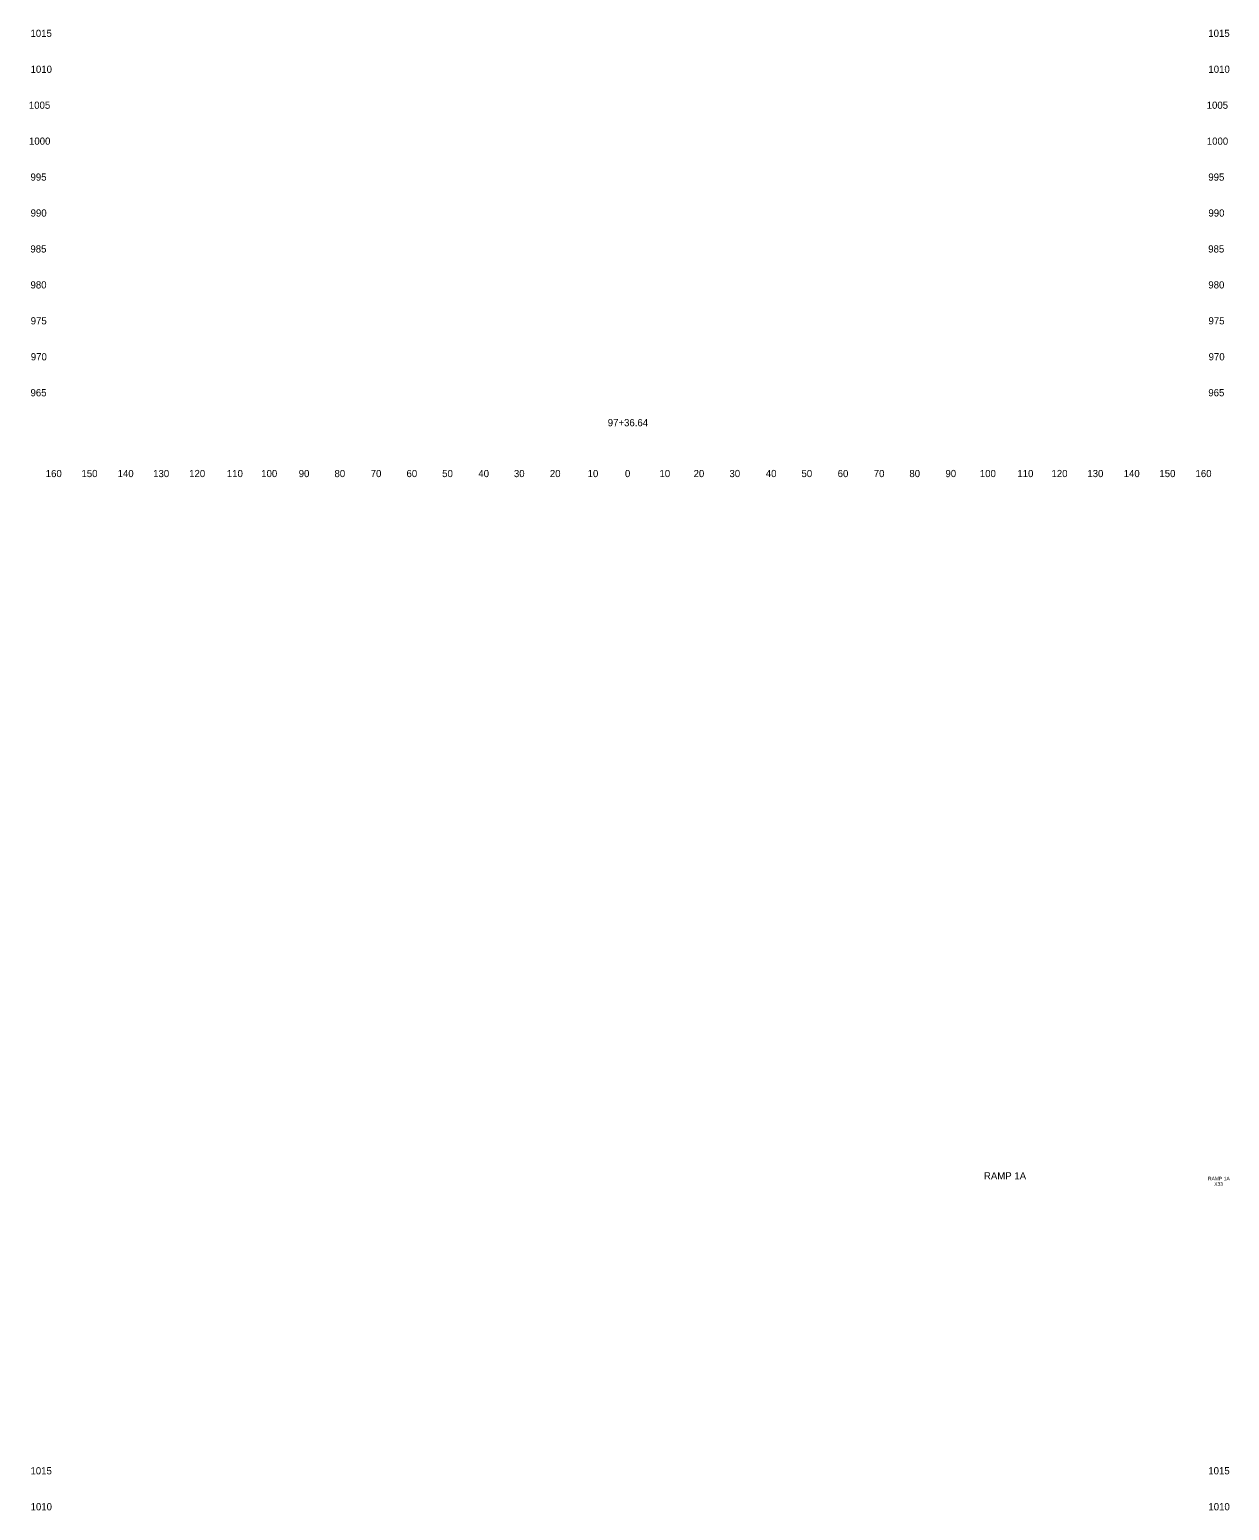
# Model space of a CAD drawing. Extents: x 4994 to 6873, y 4997 to 8804.
# Drawn here: x 6538.6 to 6872.5, y 5910 to 6322 of the extents above; entities that cross this region are included whole.
import ezdxf

# ---------------------------------------------------------------- set-up
doc = ezdxf.new("R2010")
doc.units = 0
for name, color, linetype in [('RD_SHT_ID', 7, 'Continuous'), ('RD_XS_TX_Offset', 7, 'Continuous'), ('RD_XS_TX_Station', 7, 'Continuous')]:
    doc.layers.add(name, color=color, linetype=linetype)

msp = doc.modelspace()

# ---------------------------------------------------------------- texts
at = {"layer": 'RD_SHT_ID'}
for s, height, p in [('RAMP 1A', 2, (6804.21, 6002.06)), ('RAMP 1A', 1, (6866.57, 6001.8)), ('X33', 1, (6868.29, 6000.3))]:
    msp.add_text(s, height=height, dxfattribs=at).set_placement(p)
at = {"layer": 'RD_XS_TX_Offset'}
for s, p in [('1015', (6538.85, 6320)), ('1015', (6866.65, 6320)), ('1010', (6538.88, 6310)), ('1010', (6866.68, 6310)), ('1005', (6538.4, 6300)), ('1005', (6866.2, 6300)), ('1000', (6538.44, 6290)), ('1000', (6866.24, 6290)), ('995', (6538.86, 6280)), ('995', (6866.66, 6280)), ('990', (6538.89, 6270)), ('990', (6866.69, 6270)), ('985', (6538.83, 6260)), ('985', (6866.63, 6260)), ('980', (6538.86, 6250)), ('980', (6866.66, 6250)), ('975', (6538.91, 6240)), ('975', (6866.71, 6240)), ('970', (6538.94, 6230)), ('970', (6866.74, 6230)), ('965', (6538.86, 6220)), ('965', (6866.66, 6220)), ('160', (6543.1, 6197.5)), ('150', (6553.04, 6197.5)), ('140', (6563.1, 6197.5)), ('130', (6572.99, 6197.5)), ('120', (6583.01, 6197.5)), ('110', (6593.51, 6197.5)), ('100', (6603.07, 6197.5)), ('90', (6613.5, 6197.5)), ('80', (6623.46, 6197.5)), ('70', (6633.54, 6197.5)), ('60', (6643.5, 6197.5)), ('50', (6653.43, 6197.5)), ('40', (6663.5, 6197.5)), ('30', (6673.39, 6197.5)), ('20', (6683.4, 6197.5)), ('10', (6693.91, 6197.5)), ('0', (6704.3, 6197.5)), ('0', (6704.3, 6197.5)), ('10', (6713.91, 6197.5)), ('20', (6723.4, 6197.5)), ('30', (6733.39, 6197.5)), ('40', (6743.5, 6197.5)), ('50', (6753.43, 6197.5)), ('60', (6763.5, 6197.5)), ('70', (6773.54, 6197.5)), ('80', (6783.46, 6197.5)), ('90', (6793.5, 6197.5)), ('100', (6803.07, 6197.5)), ('110', (6813.51, 6197.5)), ('120', (6823.01, 6197.5)), ('130', (6832.99, 6197.5)), ('140', (6843.1, 6197.5)), ('150', (6853.04, 6197.5)), ('160', (6863.1, 6197.5)), ('1015', (6538.85, 5920)), ('1015', (6866.65, 5920)), ('1010', (6538.88, 5910)), ('1010', (6866.68, 5910))]:
    msp.add_text(s, height=2, dxfattribs=at).set_placement(p)
at = {"layer": 'RD_XS_TX_Station'}
msp.add_text('97+36.64', height=2, dxfattribs=at).set_placement((6699.51, 6211.66))

doc.saveas('drawing.dxf')
